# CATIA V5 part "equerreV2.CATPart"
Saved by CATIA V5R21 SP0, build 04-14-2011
Part number: equerre
Bounding box of the stored display mesh (mm): x -0.995 to 17.005, y -11.441 to 6.559, z -15 to 3
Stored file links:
  C:\Users\2027.DESARCY-LEMIE30\Desktop\V16(05.04.2023)\equerreV2.CATPart
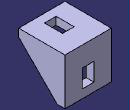
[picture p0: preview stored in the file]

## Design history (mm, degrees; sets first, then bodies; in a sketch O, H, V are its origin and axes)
Body1 (main body)
  Sketch1 on xy-plane, origin (0, 0, 0), H (1, 0, 0), V (0, 1, 0)
    line L1 (-0.9951, 6.5593) -> (17.0049, 6.5593)
    line L2 (17.0049, 6.5593) -> (17.0049, -11.4407)
    line L3 (17.0049, -11.4407) -> (-0.9951, -11.4407)
    line L4 (-0.9951, -11.4407) -> (-0.9951, 6.5593)
    length L2 = 18
    length L1 = 18
    horizontal: L1 H, L3 H
    vertical: L2 V, L4 V
  Pad1: profile Sketch1, direction (0, 0, 1), length 3
  Sketch2 on start face of Pad1, origin (0, 0, 0), H (1, 0, 0), V (0, -1, 0)
    point P1 (17.0049, -3.5593)
    reference projected line E1 (17.0049, 11.4407) -> (17.0049, -6.5593) from edge [start face of Pad1 | face of Pad1 from Sketch1.L2]
    reference projected point E2 (17.0049, -6.5593) from vertex [face of Pad1 from Sketch1.L1 | start face of Pad1 | face of Pad1 from Sketch1.L2]
    line L1 (17.0049, -3.5593) -> (17.0049, -6.5593)
    line L2 (17.0049, -3.5593) -> (-0.9951, -3.5593)
    line L3 (17.0049, -6.5593) -> (-0.9951, -6.5593)
    line L4 (-0.9951, -3.5593) -> (-0.9951, -6.5593)
    distance P1 E2 = 3
    length L2 = 18
    coincidence: P1 E1
    vertical: L1 V, L4 V
    horizontal: L2 H, L3 H
  Pad2: profile Sketch2, direction (0, 0, -1), length 15
  Sketch3 on face of Pad2, origin (17.0049, 0, 0), H (0, 1, 0), V (0, 0, 1)
    point P1 (3.5593, -15)
    point P2 (3.5593, 0)
    point P3 (-11.4407, 0)
    reference projected point E1 (-11.4407, 0) from vertex [face of Pad1 from Sketch1.L2 | start face of Pad1 | face of Pad1 from Sketch1.L3]
    reference projected point E2 (3.5593, 0) from vertex [start face of Pad1 | face of Pad2 | face of Pad2 from Sketch2.L2]
    reference projected point E3 (3.5593, -15) from vertex [face of Pad2 from Sketch2.L1 | end face of Pad2 | face of Pad2 from Sketch2.L2]
    line L1 (-11.4407, 0) -> (3.5593, 0)
    line L2 (3.5593, 0) -> (3.5593, -15)
    line L3 (-11.4407, 0) -> (3.5593, -15)
    coincidence: E1 P3, E2 P2, P1 E3
    horizontal: L1 H
    vertical: L2 V
  Pad3: profile Sketch3, direction (-1, 0, 0), length 3
  Sketch4 on face of Pad2, origin (-0.9951, 0, 0), H (0, -1, 0), V (0, 0, 1)
    point P1 (-3.5593, 0)
    point P2 (11.4407, 0)
    point P3 (-3.5593, -15)
    reference projected point E1 (-3.5593, 0) from vertex [start face of Pad1 | face of Pad2 | face of Pad2 from Sketch2.L2]
    reference projected point E2 (11.4407, 0) from vertex [face of Pad1 from Sketch1.L3 | start face of Pad1 | face of Pad1 from Sketch1.L4]
    reference projected point E3 (-3.5593, -15) from vertex [face of Pad2 from Sketch2.L4 | end face of Pad2 | face of Pad2 from Sketch2.L2]
    line L1 (-3.5593, 0) -> (11.4407, 0)
    line L2 (11.4407, 0) -> (-3.5593, -15)
    line L3 (-3.5593, 0) -> (-3.5593, -15)
    coincidence: E1 P1, E2 P2, E3 P3
    horizontal: L1 H
    vertical: L3 V
  Pad4: profile Sketch4, direction (1, 0, 0), length 3
  Sketch5 on start face of Pad1, origin (0, 0, 0), H (1, 0, 0), V (0, -1, 0)
    point P1 (10.2549, 8.1407)
    point P2 (5.7549, 8.1407)
    point P3 (10.2549, 1.1407)
    reference projected line E1 (-0.9951, -6.5593) -> (17.0049, -6.5593) from edge [face of Pad2 | end face of Pad2]
    reference projected line E2 (17.0049, 11.4407) -> (17.0049, -3.5593) from edge [face of Pad3 from Sketch3.L3 | face of Pad3]
    reference projected line E3 (-0.9951, -3.5593) -> (-0.9951, 11.4407) from edge [face of Pad4 from Sketch4.L2 | face of Pad4]
    line L1 (5.7549, 8.1407) -> (10.2549, 8.1407)
    line L2 (10.2549, 8.1407) -> (10.2549, 1.1407)
    line L3 (10.2549, 1.1407) -> (5.7549, 1.1407)
    line L4 (5.7549, 1.1407) -> (5.7549, 8.1407)
    distance P1 E1 = 14.7
    distance P1 E2 = 6.75
    distance P2 E3 = 6.75
    distance P3 P1 = 7
    horizontal: L1 H, L3 H
    vertical: L2 V, L4 V
  Pocket1: profile Sketch5, direction (0, 0, 1), length 3
  Sketch6 on face of Pad2 from Sketch2.L2, origin (0, 3.5593, 0), H (1, 0, 0), V (0, 0, 1)
    point P1 (5.7549, -4.7)
    point P2 (10.2549, -4.7)
    point P3 (5.7549, -11.7)
    reference projected line E1 (-0.9951, 3) -> (17.0049, 3) from edge [face of Pad1 from Sketch1.L3 | end face of Pad1]
    reference projected line E2 (17.0049, 0) -> (17.0049, -15) from edge [face of Pad3 from Sketch3.L3 | face of Pad3]
    reference projected line E3 (-0.9951, -15) -> (-0.9951, 0) from edge [face of Pad4 from Sketch4.L2 | face of Pad4]
    line L1 (5.7549, -4.7) -> (10.2549, -4.7)
    line L2 (5.7549, -11.7) -> (10.2549, -11.7)
    line L3 (5.7549, -4.7) -> (5.7549, -11.7)
    line L4 (10.2549, -4.7) -> (10.2549, -11.7)
    distance P3 E1 = 14.7
    distance P2 E2 = 6.75
    distance P1 E3 = 6.75
    distance P1 P3 = 7
    horizontal: L1 H, L2 H
    vertical: L3 V, L4 V
  Pocket2: profile Sketch6, direction (0, 1, 0), length 3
